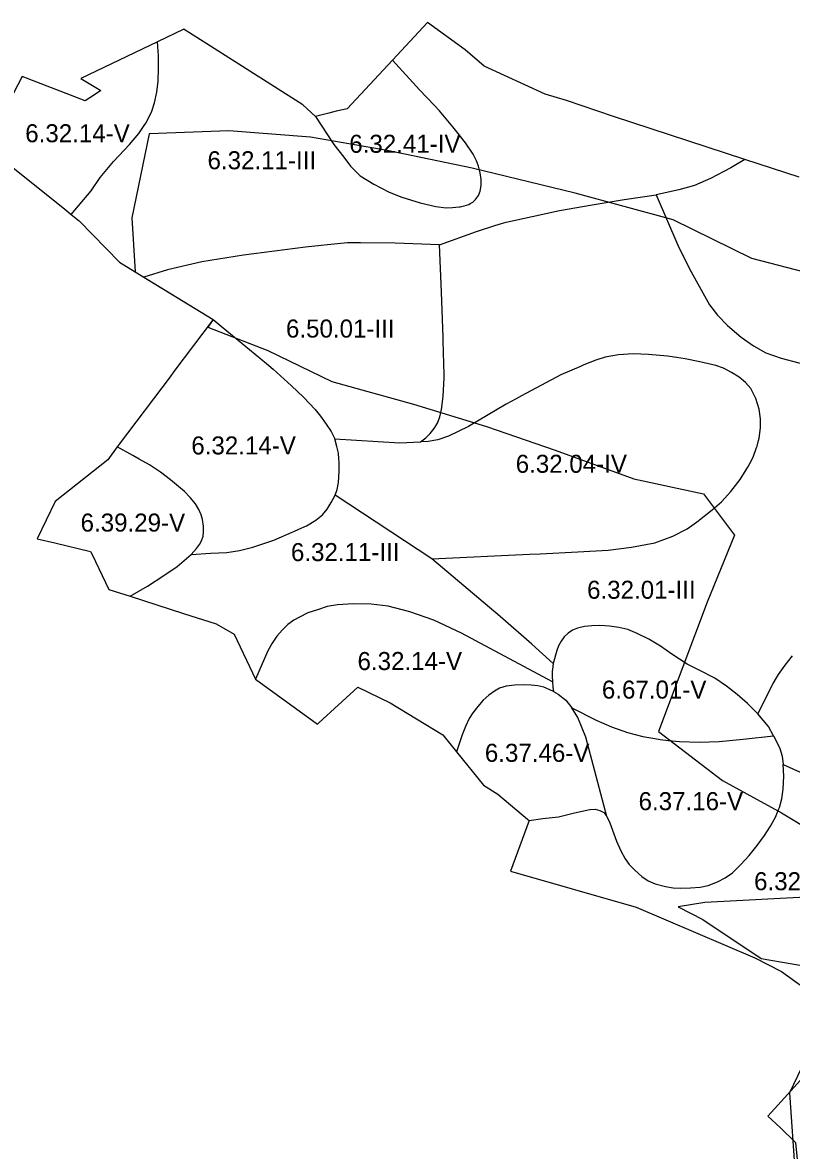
# Model space of a CAD drawing. Extents: x -555156 to -540209, y -1046851 to -1035695.
# Drawn here: x -544725 to -544298, y -1039781 to -1039156 of the extents above; entities that cross this region are included whole.
import ezdxf

# ---------------------------------------------------------------- set-up
doc = ezdxf.new("R2010")
doc.units = 0
for name, color, linetype in [('Vrstva 27', 7, 'Continuous'), ('Vrstva 28', 7, 'Continuous'), ('Vrstva 29', 7, 'Continuous')]:
    doc.layers.add(name, color=color, linetype=linetype)

msp = doc.modelspace()

# ---------------------------------------------------------------- linework, layer by layer
at = {"layer": 'Vrstva 28'}
for points in [[(-544324.11, -1039231.9), (-544396.79, -1039208.1), (-544422.95, -1039199.3), (-544434.69, -1039195.63), (-544468.57, -1039180.29), (-544479.18, -1039171.2), (-544499.94, -1039156.03), (-544519.46, -1039176.94)], [(-544562.15, -1039208.08), (-544569.22, -1039201.72), (-544632.08, -1039161.69), (-544634.47, -1039160.17), (-544635.1, -1039159.77), (-544649.79, -1039166.76)], [(-544649.79, -1039166.76), (-544692.27, -1039186.97), (-544681.14, -1039193.72), (-544684.72, -1039196.01), (-544689.98, -1039199.38), (-544724.88, -1039185.85), (-544737.14, -1039209.41), (-544737.49, -1039210.08), (-544745.04, -1039224.6), (-544701.14, -1039259.53), (-544697.57, -1039262.38)], [(-544650.18, -1039194.57), (-544649.43, -1039188.44), (-544649.13, -1039181.57), (-544649.13, -1039174.54), (-544649.79, -1039166.76)], [(-544519.46, -1039176.94), (-544544.6, -1039203.87), (-544549.75, -1039204.94), (-544550.61, -1039205.12), (-544554.7, -1039206.17), (-544562.15, -1039208.08)], [(-544486.11, -1039258.61), (-544482.52, -1039258.18), (-544481.9, -1039258.07), (-544479.62, -1039257.67), (-544477.06, -1039256.82), (-544476.34, -1039256.39), (-544474.92, -1039255.54), (-544473.39, -1039254.08), (-544471.77, -1039251.95), (-544470.74, -1039249.47), (-544470.23, -1039246.4), (-544470.32, -1039243.07), (-544470.74, -1039239.23), (-544471.68, -1039235.55), (-544472.88, -1039232.65), (-544474.75, -1039228.98), (-544479.03, -1039222.77), (-544483.75, -1039216.61), (-544485.9, -1039213.8), (-544493.37, -1039204.99), (-544496.16, -1039202.05), (-544504.42, -1039193.33), (-544519.46, -1039176.94)], [(-544697.57, -1039262.38), (-544686.62, -1039249.27), (-544681.54, -1039241.94), (-544674.23, -1039232.98), (-544665.26, -1039223.56), (-544660.18, -1039217.58), (-544656.79, -1039212.55), (-544656.15, -1039211.6), (-544655.08, -1039209.52), (-544653.16, -1039205.78), (-544651.37, -1039200.55), (-544650.18, -1039194.57)], [(-544562.15, -1039208.08), (-544551.97, -1039223.55), (-544546.45, -1039230.57), (-544542.71, -1039235.65), (-544537.33, -1039240.89), (-544529.72, -1039245.67), (-544521.35, -1039250), (-544514.18, -1039252.84), (-544504.17, -1039255.98), (-544495.36, -1039257.92), (-544489.69, -1039258.67), (-544486.11, -1039258.61)], [(-544324.11, -1039231.9), (-544331.88, -1039236.54), (-544343.08, -1039242.37), (-544351.89, -1039246.26), (-544360.71, -1039248.8), (-544373.25, -1039251.49)], [(-544293.9, -1039241.79), (-544324.11, -1039231.9)], [(-544408.65, -1039257.02), (-544390.88, -1039254.03), (-544373.25, -1039251.49)], [(-544373.25, -1039251.49), (-544361.19, -1039279.46), (-544354.66, -1039292.53), (-544347.34, -1039305.87), (-544343.62, -1039312.4), (-544343.55, -1039312.49), (-544339.14, -1039318.23), (-544333.61, -1039323.91), (-544326, -1039330.33), (-544319.27, -1039335.27), (-544312.4, -1039339.15)], [(-544493.38, -1039279.16), (-544472.88, -1039271.81), (-544462.6, -1039268.49), (-544458.99, -1039267.33), (-544456.42, -1039266.74), (-544441.96, -1039263.44), (-544426.73, -1039260.15), (-544408.65, -1039257.02)], [(-544697.57, -1039262.38), (-544693.22, -1039265.84), (-544670.81, -1039288.9), (-544657.33, -1039297.16)], [(-544493.38, -1039279.16), (-544517.95, -1039278.37), (-544537.1, -1039278.18), (-544544.35, -1039278.11), (-544555.56, -1039279.24), (-544559.07, -1039279.6), (-544567.61, -1039280.46), (-544602.12, -1039284.91), (-544625.12, -1039288.57), (-544644.2, -1039293.02), (-544657.33, -1039297.16)], [(-544503.93, -1039388.31), (-544500.95, -1039386.17), (-544498.47, -1039383.87), (-544496.25, -1039380.96), (-544494.55, -1039377.97), (-544493.18, -1039374.47), (-544492.24, -1039370.54), (-544491.35, -1039363.22), (-544490.79, -1039352.98), (-544491.02, -1039343.34), (-544491.08, -1039340.75), (-544491.32, -1039330.48), (-544492.32, -1039305.51), (-544493.38, -1039279.16)], [(-544657.33, -1039297.16), (-544618.92, -1039320.67)], [(-544312.4, -1039339.15), (-544303.89, -1039341.99), (-544294.03, -1039344.68), (-544281.04, -1039346.62), (-544264.75, -1039348.12), (-544251.55, -1039348.76), (-544246.08, -1039349.02), (-544231.3, -1039349.32), (-544219.94, -1039348.72), (-544207.4, -1039347.67), (-544196.34, -1039346.18), (-544181.71, -1039343.49), (-544167.37, -1039339.45), (-544154.53, -1039335.17), (-544153.92, -1039334.97), (-544150.63, -1039333.5), (-544138.84, -1039328.24), (-544123.9, -1039318.68), (-544121.01, -1039316.53), (-544110.01, -1039308.37), (-544099.25, -1039298.35)], [(-544618.92, -1039320.67), (-544640.67, -1039349.48), (-544642.82, -1039352.33), (-544670.99, -1039389.65), (-544672.08, -1039391.15)], [(-544618.92, -1039320.67), (-544614.42, -1039324.38), (-544589.37, -1039345), (-544585.66, -1039348.06), (-544575.5, -1039357.32), (-544568.78, -1039363.6), (-544562.36, -1039370.41), (-544559.45, -1039374.17), (-544556.21, -1039378.52), (-544553.39, -1039382.62), (-544551.43, -1039386.72)], [(-544316.47, -1039387.63), (-544316.15, -1039386.34), (-544315.4, -1039380.63), (-544315.4, -1039375.67), (-544316.17, -1039370.29), (-544317.87, -1039364.4), (-544320.78, -1039358.93), (-544323.59, -1039355.6), (-544327.26, -1039352.62), (-544331.36, -1039350.05), (-544335.8, -1039347.66), (-544340.08, -1039346.08), (-544349.04, -1039343.99), (-544357.1, -1039342.35), (-544361.85, -1039341.63), (-544365.58, -1039341.06), (-544366.96, -1039340.85), (-544377.42, -1039339.95), (-544385.93, -1039339.66), (-544394.15, -1039340.25), (-544401.47, -1039341.45), (-544406.69, -1039343.09), (-544413.27, -1039345.78), (-544415.2, -1039346.6), (-544426.13, -1039351.25), (-544447.95, -1039362.98), (-544450.88, -1039364.55), (-544456.45, -1039367.54), (-544477.36, -1039379.94), (-544488.42, -1039385.32), (-544494.24, -1039387.26), (-544499.62, -1039388.16), (-544503.93, -1039388.31)], [(-544551.32, -1039418.05), (-544550.21, -1039414.8), (-544549.45, -1039410.87), (-544548.96, -1039404.66), (-544548.96, -1039399.62), (-544549.12, -1039397.78), (-544549.38, -1039394.75), (-544549.54, -1039394.02), (-544550.24, -1039390.91), (-544551.43, -1039386.72)], [(-544551.43, -1039386.72), (-544515.45, -1039388.87), (-544503.93, -1039388.31)], [(-544497.62, -1039453.31), (-544443.52, -1039450.71), (-544437.48, -1039450.42), (-544416.57, -1039449.42), (-544399.84, -1039448.37), (-544386.85, -1039446.73), (-544374, -1039444.34), (-544363.99, -1039440.6), (-544356.08, -1039436.57), (-544349.58, -1039431.95), (-544349.09, -1039431.6), (-544346.62, -1039429.64), (-544342.09, -1039426.05), (-544337.06, -1039421.61), (-544331.85, -1039415.97), (-544326.56, -1039409.22), (-544323.32, -1039404), (-544322.38, -1039402.48), (-544321.31, -1039400.41), (-544319.47, -1039396.84), (-544317.49, -1039391.48), (-544317.26, -1039390.86), (-544316.47, -1039387.63)], [(-544672.08, -1039391.15), (-544677.29, -1039398.35), (-544706.53, -1039421.42), (-544716.57, -1039442.13), (-544706.76, -1039444.44), (-544686.84, -1039449.14), (-544685.99, -1039450.91), (-544676.73, -1039470.15), (-544664.95, -1039473.94)], [(-544631.03, -1039450.76), (-544628.1, -1039447.6), (-544626.4, -1039445.38), (-544625.29, -1039443.24), (-544624.43, -1039440.68), (-544624.18, -1039438.29), (-544624.26, -1039435.21), (-544624.86, -1039431.37), (-544625.63, -1039428.81), (-544626.82, -1039425.82), (-544628.7, -1039422.83), (-544631.6, -1039419.33), (-544634.85, -1039415.91), (-544642.59, -1039409.38), (-544648.06, -1039405.2), (-544654.29, -1039401.18), (-544659.86, -1039397.95), (-544663.42, -1039395.89), (-544672.08, -1039391.15)], [(-544620.12, -1039450.16), (-544611.31, -1039449.71), (-544604.29, -1039448.66), (-544596.82, -1039446.72), (-544585.32, -1039442.84), (-544575.09, -1039438.53), (-544574.11, -1039438.12), (-544571.43, -1039436.87), (-544567.11, -1039434.87), (-544561.91, -1039431.88), (-544558.32, -1039428.89), (-544555.76, -1039425.65), (-544553.37, -1039422.06), (-544551.32, -1039418.05)], [(-544497.62, -1039453.31), (-544551.32, -1039418.05)], [(-544655.23, -1039468.39), (-544646.18, -1039462.5), (-544638.84, -1039457.46), (-544631.03, -1039450.76)], [(-544631.03, -1039450.76), (-544620.12, -1039450.16)], [(-544430.38, -1039511.29), (-544442.14, -1039500.57), (-544459.65, -1039485.14), (-544497.62, -1039453.31)], [(-544664.95, -1039473.94), (-544655.23, -1039468.39)], [(-544664.95, -1039473.94), (-544635.29, -1039483.49), (-544617.17, -1039489.32), (-544607.24, -1039495.04), (-544595.46, -1039519.93)], [(-544430.7, -1039521.41), (-544481.16, -1039494.35), (-544496.54, -1039487.17), (-544509.84, -1039482.69), (-544521.79, -1039479.55), (-544531.35, -1039478.36), (-544541.05, -1039478.21), (-544549.86, -1039478.69), (-544555.75, -1039479.71), (-544561.12, -1039481.42), (-544566.42, -1039483.21), (-544571.02, -1039485.52), (-544574.18, -1039487.23), (-544577.51, -1039489.7), (-544580.67, -1039492.78), (-544583.57, -1039496.11), (-544586.22, -1039499.95), (-544588.52, -1039504.22), (-544595.46, -1039519.93)], [(-544316.79, -1039539.22), (-544322.58, -1039533.39), (-544328.21, -1039528.35), (-544334.27, -1039523.82), (-544340.76, -1039519.47), (-544349.38, -1039515.03), (-544355.95, -1039511.53), (-544364.46, -1039506.17), (-544370.78, -1039501.73), (-544377.27, -1039497.8), (-544383.75, -1039494.55), (-544388.96, -1039492.5), (-544393.83, -1039491.31), (-544399.12, -1039490.54), (-544404.49, -1039490.2), (-544408.93, -1039490.37), (-544412.94, -1039490.8), (-544416.79, -1039491.65), (-544419.52, -1039492.76), (-544421.99, -1039494.38), (-544424.21, -1039496.52), (-544425.92, -1039498.82), (-544427.37, -1039501.47), (-544428.39, -1039504.03), (-544430.38, -1039511.29)], [(-544297.76, -1039507.07), (-544301.86, -1039512.19), (-544305.62, -1039517.4), (-544306.7, -1039519.28), (-544308.47, -1039522.39), (-544309.03, -1039523.38), (-544316.79, -1039539.22)], [(-544430.38, -1039511.29), (-544430.72, -1039514.63), (-544430.8, -1039515.46), (-544430.8, -1039518.11), (-544430.8, -1039518.29), (-544430.7, -1039521.41)], [(-544595.46, -1039519.93), (-544592.66, -1039521.96), (-544561.76, -1039544.38), (-544561.12, -1039544.84), (-544560.36, -1039544.14), (-544538.73, -1039524.34), (-544520.7, -1039533.13), (-544491.45, -1039550.79), (-544483.87, -1039560.24)], [(-544430.15, -1039526.82), (-544432.09, -1039525.77), (-544435.59, -1039524.41), (-544438.75, -1039523.64), (-544442.61, -1039523.28), (-544446.62, -1039523.11), (-544451.57, -1039523.28), (-544456.44, -1039523.88), (-544460.02, -1039524.99), (-544462.84, -1039526.61), (-544466, -1039528.83), (-544469.16, -1039531.57), (-544472.14, -1039535.15), (-544474.96, -1039538.65), (-544476.92, -1039541.73), (-544478.97, -1039546.17), (-544480.77, -1039550.87), (-544483.87, -1039560.24)], [(-544430.7, -1039521.41), (-544430.45, -1039524.34), (-544430.15, -1039526.82)], [(-544430.15, -1039526.82), (-544427.48, -1039528.25), (-544423.39, -1039531.5), (-544419.89, -1039535.85)], [(-544412.2, -1039552.16), (-544414.17, -1039547.12), (-544416.73, -1039541.15), (-544419.89, -1039535.85)], [(-544419.89, -1039535.85), (-544406.46, -1039542.57), (-544397.93, -1039546.33), (-544389.05, -1039549.49), (-544380.69, -1039551.62), (-544373.95, -1039552.81), (-544371.04, -1039553.33), (-544366.46, -1039553.84), (-544360.2, -1039554.53)], [(-544308.09, -1039551.4), (-544310.97, -1039546.23), (-544316.79, -1039539.22)], [(-544338.18, -1039554.44), (-544324.87, -1039553.16), (-544308.09, -1039551.4)], [(-544308.09, -1039551.4), (-544307.98, -1039551.61), (-544304.54, -1039558.33), (-544303.35, -1039562.52), (-544302.75, -1039567.15)], [(-544400.53, -1039596.03), (-544412.2, -1039552.16)], [(-544360.2, -1039554.53), (-544349.36, -1039554.87), (-544338.18, -1039554.44)], [(-544483.87, -1039560.24), (-544469.03, -1039578.73), (-544461.07, -1039583.76), (-544444.6, -1039597.44), (-544443.71, -1039598.18)], [(-544400.53, -1039596.03), (-544398.87, -1039599.62), (-544395.12, -1039609.65), (-544392.81, -1039615.11), (-544390.42, -1039619.55), (-544388.12, -1039622.71), (-544385.13, -1039625.79), (-544381.23, -1039629.26), (-544377.56, -1039631.74), (-544373.72, -1039633.44), (-544368.08, -1039634.9), (-544363.73, -1039635.66), (-544359.63, -1039635.83), (-544354.09, -1039635.66), (-544348.79, -1039635.15), (-544344.36, -1039634.21), (-544339.15, -1039632.18), (-544334.97, -1039630.05), (-544330.96, -1039627.23), (-544326.18, -1039622.7), (-544321.65, -1039617.75), (-544317.13, -1039612.11), (-544313.12, -1039606.65), (-544309.79, -1039601.44), (-544306.93, -1039596.14), (-544306.64, -1039595.43), (-544305.31, -1039592.19), (-544304.84, -1039591.06), (-544303.5, -1039586.28), (-544302.75, -1039580.9), (-544302.45, -1039573.73), (-544302.75, -1039567.15)], [(-544302.75, -1039567.15), (-544288.32, -1039573.75), (-544279.66, -1039578.68), (-544271.89, -1039583.91), (-544265.62, -1039588.69), (-544259.85, -1039593.78), (-544255.76, -1039598.3), (-544252.26, -1039602.83), (-544249.27, -1039607.27), (-544246.54, -1039611.54), (-544243.81, -1039616.15), (-544241.5, -1039621.45), (-544240.12, -1039626.65), (-544238.84, -1039632.38), (-544238.49, -1039634.54)], [(-544443.71, -1039598.18), (-544436.03, -1039597.22), (-544427.33, -1039596.28), (-544418.45, -1039593.98), (-544410, -1039592.1), (-544407.01, -1039592.01), (-544404.37, -1039592.7), (-544402.23, -1039593.89), (-544400.53, -1039596.03)], [(-544443.71, -1039598.18), (-544453.98, -1039626.34), (-544384.32, -1039646.27), (-544318.42, -1039674.46), (-544303.72, -1039682.01), (-544286.59, -1039694.27)], [(-544286.59, -1039694.27), (-544280.35, -1039698.73), (-544269.21, -1039706.69), (-544264.36, -1039710.16), (-544265.92, -1039711.95), (-544276.58, -1039723.86), (-544279.1, -1039726.68), (-544302, -1039751.89), (-544311.24, -1039762.06), (-544304.47, -1039768.49), (-544295.86, -1039776.66), (-544291.48, -1039821.68), (-544288.66, -1039833.78), (-544281.17, -1039865.86), (-544284.72, -1039871.32), (-544291.97, -1039882.48)]]:
    msp.add_lwpolyline(points, dxfattribs=at)
at = {"layer": 'Vrstva 29'}
for points in [[(-544285.979004, -1039295.661011), (-544320.130005, -1039286.750977), (-544363.820984, -1039265.445007), (-544418.091003, -1039250.508972), (-544475.291016, -1039236.820007), (-544522.377991, -1039226.912903), (-544564.848999, -1039219.492004), (-544610.265015, -1039216.119995), (-544654.369995, -1039217.718994), (-544663.953003, -1039264.211975), (-544662.069094, -1039294.251678), (-544618.92, -1039320.67), (-544621.7861, -1039324.861935), (-544588.494019, -1039337.794006), (-544553.094971, -1039354.982971), (-544507.794006, -1039367.521912), (-544467.328003, -1039379.848022), (-544429.237976, -1039392.963989), (-544385.542908, -1039408.916992), (-544346.991028, -1039417.23291), (-544329.765991, -1039440.059021), (-544344.85199, -1039477.35199), (-544371.922974, -1039548.921997), (-544336.458984, -1039576.060913), (-544303.689026, -1039594.016907), (-544268.426025, -1039615.271912)], [(-544283.10498, -1039640.367004), (-544346.286011, -1039643.690979), (-544360.928964, -1039646.139066), (-544347.29, -1039653.07), (-544315.06, -1039674.66), (-544280.66, -1039680.59)], [(-544283.69, -1039716.79), (-544299.3, -1039749.2), (-544296.18, -1039794.66)]]:
    msp.add_lwpolyline(points, dxfattribs=at)

# ---------------------------------------------------------------- texts
at = {"layer": 'Vrstva 27'}
for s, p in [('6.32.14-V', (-544723.120884, -1039222.37)), ('6.32.41-IV', (-544543.407241, -1039228.21)), ('6.32.11-III', (-544622.023926, -1039237.34)), ('6.50.01-III', (-544578.516548, -1039330.62)), ('6.32.14-V', (-544631.010884, -1039395.41)), ('6.32.04-IV', (-544451.097119, -1039405.57)), ('6.39.29-V', (-544692.420459, -1039438.14)), ('6.32.11-III', (-544575.756548, -1039454.51)), ('6.32.01-III', (-544411.516548, -1039475.39)), ('6.32.14-V', (-544538.840884, -1039514.89)), ('6.67.01-V', (-544403.311006, -1039530.71)), ('6.37.46-V', (-544468.217974, -1039565.76)), ('6.37.16-V', (-544382.957974, -1039592.56)), ('6.32.11-III', (-544318.896548, -1039636.92))]:
    msp.add_text(s, height=10, dxfattribs=at).set_placement(p)

doc.saveas('drawing.dxf')
